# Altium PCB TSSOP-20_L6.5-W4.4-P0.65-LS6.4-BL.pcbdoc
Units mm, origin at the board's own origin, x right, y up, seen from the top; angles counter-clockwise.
Board outline 19.74 x 20.19 mm, 2 copper layers (Top Layer, Bottom Layer), stack 0 mm thick; 1 components, 0 nets, 20 pads, 0 vias.
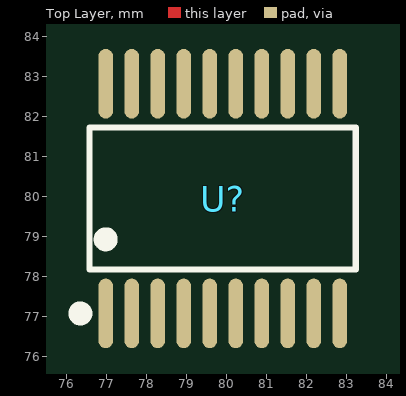
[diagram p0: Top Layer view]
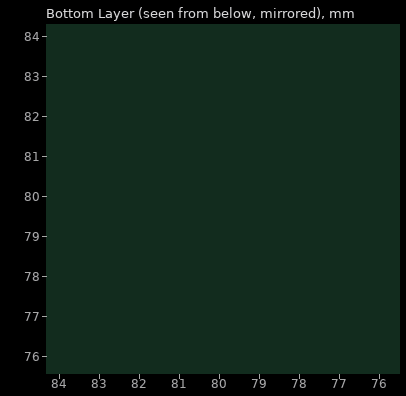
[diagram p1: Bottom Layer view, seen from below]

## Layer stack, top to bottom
Top Layer: signal copper (thickness not stored)
Bottom Layer: signal copper (thickness not stored)

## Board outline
89.586,69.85 69.85,69.85 69.85,90.042 89.586,90.042

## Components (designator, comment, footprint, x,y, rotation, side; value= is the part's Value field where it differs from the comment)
U? "" TSSOP-20_L6.5-W4.4-P0.65-LS6.4-BL 79.909,79.95 r0 top

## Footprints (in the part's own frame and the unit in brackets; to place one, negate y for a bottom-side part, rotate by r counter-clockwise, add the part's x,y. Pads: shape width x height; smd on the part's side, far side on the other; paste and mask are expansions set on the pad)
TSSOP-20_L6.5-W4.4-P0.65-LS6.4-BL [mm]
  oval 0.364x1.742 smd: 1(-2.925,-2.871) 2(-2.275,-2.871) 3(-1.625,-2.871) 4(-0.975,-2.871) 5(-0.325,-2.871) 6(0.325,-2.871) 7(0.975,-2.871) 8(1.625,-2.871) 9(2.275,-2.871) 10(2.925,-2.871) 11(2.925,2.871) 12(2.275,2.871) 13(1.625,2.871) 14(0.975,2.871) 15(0.325,2.871) 16(-0.325,2.871) 17(-0.975,2.871) 18(-1.625,2.871) 19(-2.275,2.871) 20(-2.925,2.871)
  silkscreen extent -3.71,-3.02 3.33,1.77

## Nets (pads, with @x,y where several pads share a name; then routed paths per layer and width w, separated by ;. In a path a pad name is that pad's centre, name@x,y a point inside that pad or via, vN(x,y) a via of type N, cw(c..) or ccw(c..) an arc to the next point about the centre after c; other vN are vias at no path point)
pads on no net: U?.1 U?.2 U?.3 U?.4 U?.5 U?.6 U?.7 U?.8 U?.9 U?.10 U?.11 U?.12 U?.13 U?.14 U?.15 U?.16 U?.17 U?.18 U?.19 U?.20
